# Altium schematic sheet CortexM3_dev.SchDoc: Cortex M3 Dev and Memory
size A4; DrawnBy: Watzek; Organization: HTL Hollabrunn; Address1: Abteilung Elektronik; Address2: Anton Ehrenfried-Straße 10; Address3: 2020 Hollabrunn; DocumentNumber: 06; Revision: 01; SheetNumber: 06; SheetTotal: 06; SPICEModelCacheGTJPSRCJ: <root> / <DocumentId>GTJPSRCJ</DocumentId> / <CacheFrame Number="0"> / <Model Name="led0" Kind="MDL"> / <Text>*Typ INFRARED GaAs LED: Vf=1.2V Vr=5V If=40mA trr=3uS / *LED Pinout: 1=A, 2=K / .MODEL LED0 D (IS=93.5P RS=84M N=2.63 BV=5 IBV=10U / + CJO=2.97P VJ=.75 M=.333 TT=4.32U)</Text> / </Model> / <Model Name="cap" Kind="MDL"> / <Text>*Default semiconductor capacitor / .MODEL CAP C()</Text> / </Model> / </CacheFrame> / </root>
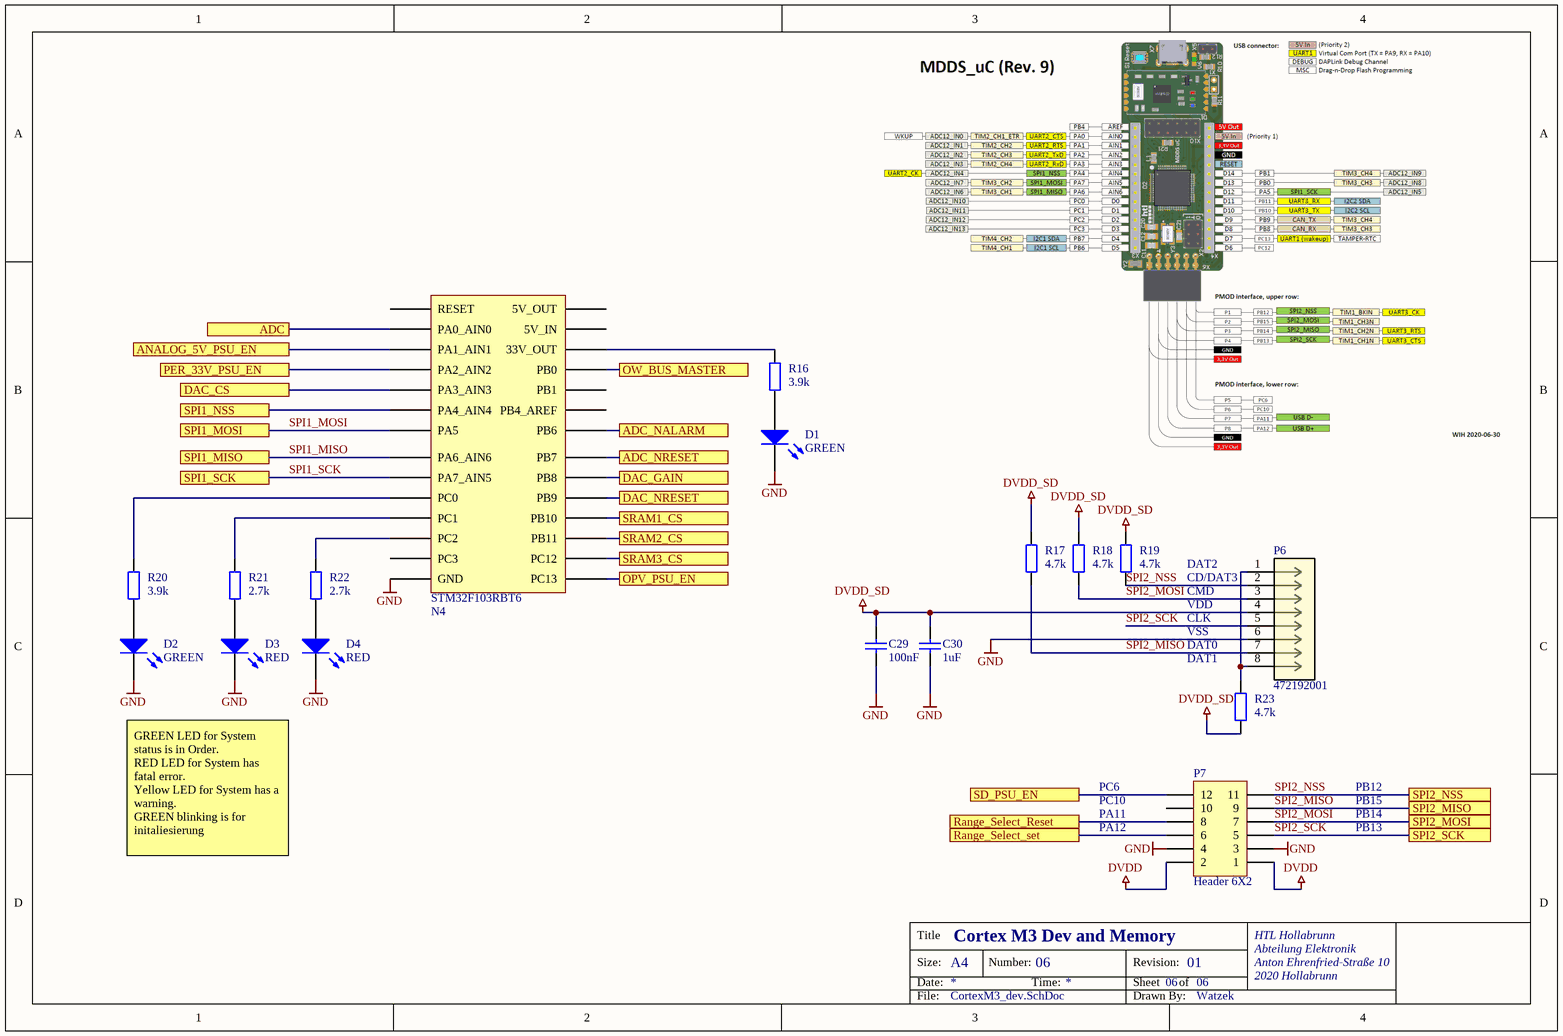
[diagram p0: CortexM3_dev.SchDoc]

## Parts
C29  100nF  [C1206-KUE]
C30  1uF  [C1206-KUE]
D1  GREEN  [6-0805_N-KUE]
D2  GREEN  [6-0805_N-KUE]
D3  RED  [6-0805_N-KUE]
D4  RED  [6-0805_N-KUE]
N4  STM32F103  [DIP28]  (value not drawn)
P6  472192001  [CONN_47219-2001_MOL]
P7  Header 6X2  [HDR2X6]
R16  3.9k  [C1206-KUE]
R17  4.7k  [C1206-KUE]
R18  4.7k  [C1206-KUE]
R19  4.7k  [C1206-KUE]
R20  3.9k  [C1206-KUE]
R21  2.7k  [C1206-KUE]
R22  2.7k  [C1206-KUE]
R23  4.7k  [C1206-KUE]

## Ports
ADC, ADC_NALARM, ADC_NRESET, ANALOG_5V_PSU_EN, DAC_CS, DAC_GAIN, DAC_NRESET, OPV_PSU_EN, OW_BUS_MASTER, PER_33V_PSU_EN, Range_Select_Reset, Range_Select_set, SD_PSU_EN, SPI1_MISO, SPI1_MOSI, SPI1_NSS, SPI1_SCK, SPI2_MISO, SPI2_MOSI, SPI2_NSS, SPI2_SCK, SRAM1_CS, SRAM2_CS, SRAM3_CS

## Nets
DVDD: P7.1 P7.2
DVDD_SD: C29.2 C30.2 P6.4 R17.1 R18.1 R19.1 R23.2
GND: C29.1 C30.1 D1.2(K) D2.2(K) D3.2(K) D4.2(K) N4.18(GND) P6.6 P7.3 P7.4
ADC: N4.2(PA0_AIN0) ; port ADC
ADC_NALARM: N4.14(PB6) ; port ADC_NALARM
ADC_NRESET: N4.13(PB7) ; port ADC_NRESET
ANALOG_5V_PSU_EN: N4.3(PA1_AIN1) ; port ANALOG_5V_PSU_EN
DAC_CS: N4.5(PA3_AIN3) ; port DAC_CS
DAC_GAIN: N4.26(PB8) ; port DAC_GAIN
DAC_NRESET: N4.25(PB9) ; port DAC_NRESET
OPV_PSU_EN: N4.27(PC13) ; port OPV_PSU_EN
OW_BUS_MASTER: N4.21(PB0) ; port OW_BUS_MASTER
PER_33V_PSU_EN: N4.4(PA2_AIN2) ; port PER_33V_PSU_EN
Range_Select_Reset: P7.8 ; port Range_Select_Reset
Range_Select_set: P7.6 ; port Range_Select_set
SD_PSU_EN: P7.12 ; port SD_PSU_EN
SPI1_MISO: N4.8(PA6_AIN6) ; port SPI1_MISO
SPI1_MOSI: N4.22(PA5) ; port SPI1_MOSI
SPI1_NSS: N4.6(PA4_AIN4) ; port SPI1_NSS
SPI1_SCK: N4.7(PA7_AIN5) ; port SPI1_SCK
SPI2_MISO: P6.7 P7.9 R17.2 ; port SPI2_MISO
SPI2_MOSI: P6.3 P7.7 R18.2 ; port SPI2_MOSI
SPI2_NSS: P6.2 P7.11 R19.2 ; port SPI2_NSS
SPI2_SCK: P6.5 P7.5 ; port SPI2_SCK
SRAM1_CS: N4.24(PB10) ; port SRAM1_CS
SRAM2_CS: N4.23(PB11) ; port SRAM2_CS
SRAM3_CS: N4.28(PC12) ; port SRAM3_CS
NetD1_1: D1.1(A) R16.2
NetD2_1: D2.1(A) R20.2
NetD3_1: D3.1(A) R21.2
NetD4_1: D4.1(A) R22.2
NetN4_9: N4.9(PC0) R20.1
NetN4_10: N4.10(PC1) R21.1
NetN4_11: N4.11(PC2) R22.1
NetN4_17: N4.17(33V_OUT) R16.1
NetP6_1: P6.1 P6.8 R23.1

Not connected (* = marked no-connect by the designer): N4 1(PB4_AREF) 12(PC3) 15(5V_OUT) 16(5V_IN) 19(RESET) 20(PB1); P7 10

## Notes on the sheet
- DAT2
- CD/DAT3
- CMD
- VDD
- CLK
- VSS
- DAT0
- DAT1
- PC6
- PB12
- GREEN LED for System status is in Order.
  RED LED for System has fatal error.
  Yellow LED for System has a warning.
  GREEN blinking is for initaliesierung
- PC10
- PA11
- PA12
- PB15
- PB14
- PB13
- Labels drawn without touching a wire or pin: SPI2_NSS

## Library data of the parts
C29 C30 = Capacitor: Manufacturer: Kemet; Bezeichnung: Kerko +-10% 63V
D1-D4 = LED0: Typical INFRARED GaAs LED
P6 = 472192001: 1.10mm Pitch microSD Card Connector, Hinge Type, Lead-Free; Manufacturer_Name: Molex Connector Corporation
P7 = Header 6X2: Header, 6-Pin, Dual row
R16-R23 = ResistorSMD: Resistor SMD; Manufacturer: AVX; Bezeichnung: SMD Wid. 1/8W 2%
